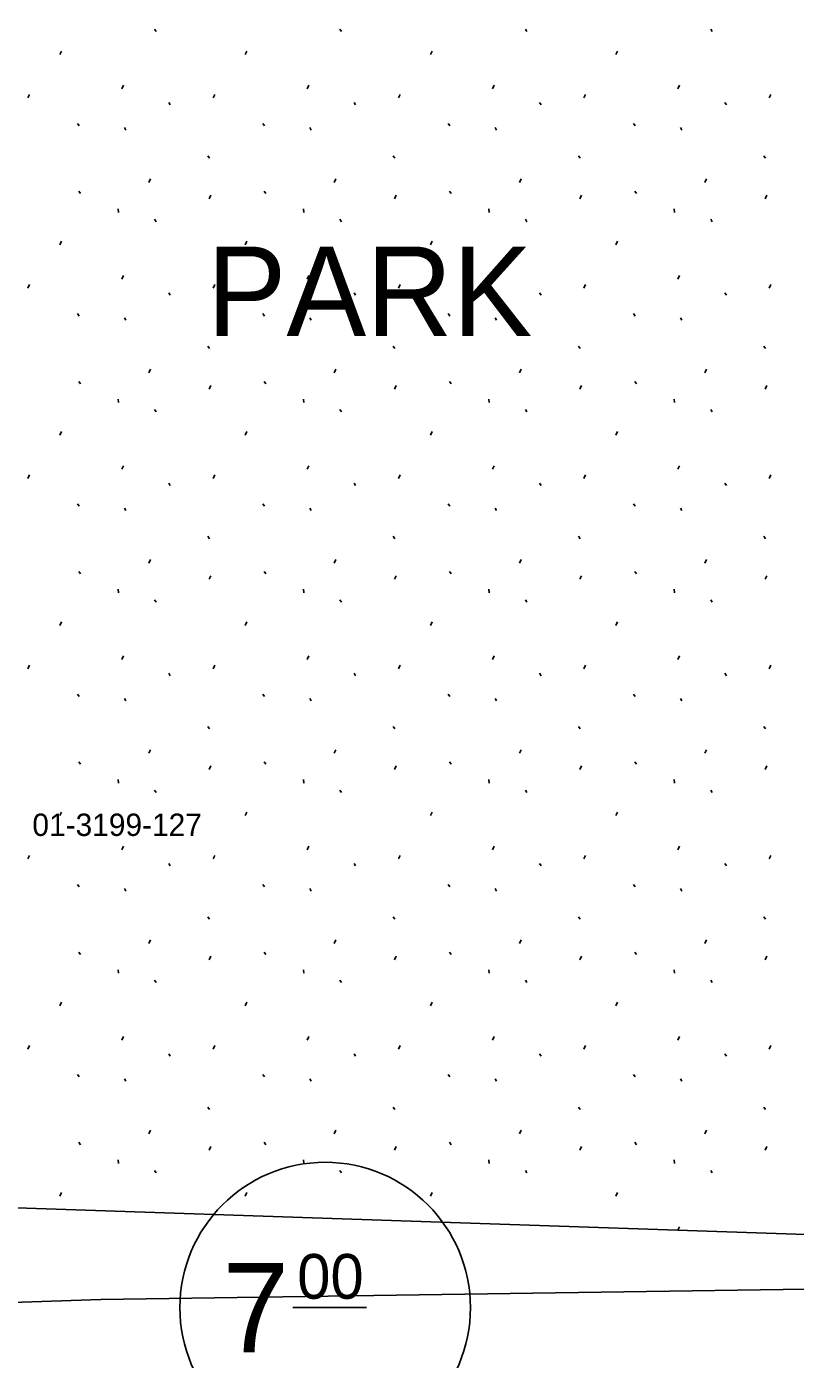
# Model space of a CAD drawing. Extents: x 419396 to 421519, y 4453567 to 4456767.
# Drawn here: x 421074.7 to 421109.1, y 4454902 to 4454961.6 of the extents above; entities that cross this region are included whole.
import ezdxf

# ---------------------------------------------------------------- set-up
doc = ezdxf.new("R2010")
doc.units = 0
for name, color, linetype in [('0_KADASTRO', 7, 'Continuous'), ('Level 28', 7, 'Continuous'), ('Level 41', 7, 'Continuous'), ('Level 58', 7, 'Continuous'), ('Level 61', 7, 'Continuous')]:
    doc.layers.add(name, color=color, linetype=linetype)

msp = doc.modelspace()

# ---------------------------------------------------------------- linework, layer by layer
at = {"layer": '0_KADASTRO'}
msp.add_lwpolyline([(421037.46, 4454903.29), (421040.2, 4454969.38), (421075.94, 4454970.4), (421108.85, 4454973.43), (421116.5, 4454972.91), (421125.86, 4454961.42), (421128.66, 4454942.34), (421125.36, 4454924.69), (421124.84, 4454912.07), (421127.9, 4454905.39), (421078.04, 4454904.65)], close=True, dxfattribs=at)
at = {"layer": 'Level 28'}
msp.add_line((421135.782, 4454906.666), (421051.306, 4454909.537), dxfattribs=at)
at = {"layer": 'Level 41'}
for p, q in [((421080.449, 4454961.486), (421080.519, 4454961.379)), ((421088.742, 4454961.486), (421088.812, 4454961.379)), ((421097.035, 4454961.486), (421097.105, 4454961.379)), ((421105.328, 4454961.486), (421105.398, 4454961.379)), ((421076.212, 4454960.342), (421076.284, 4454960.502)), ((421084.505, 4454960.342), (421084.577, 4454960.502)), ((421092.798, 4454960.342), (421092.87, 4454960.502)), ((421101.091, 4454960.342), (421101.163, 4454960.502)), ((421074.774, 4454958.404), (421074.845, 4454958.564)), ((421078.984, 4454958.812), (421079.054, 4454958.972)), ((421083.067, 4454958.404), (421083.138, 4454958.564)), ((421087.277, 4454958.812), (421087.347, 4454958.972)), ((421091.36, 4454958.404), (421091.431, 4454958.564)), ((421095.57, 4454958.812), (421095.64, 4454958.972)), ((421099.653, 4454958.404), (421099.724, 4454958.564)), ((421103.863, 4454958.812), (421103.933, 4454958.972)), ((421107.946, 4454958.404), (421108.017, 4454958.564)), ((421081.079, 4454958.196), (421081.15, 4454958.09)), ((421089.372, 4454958.196), (421089.443, 4454958.09)), ((421097.665, 4454958.196), (421097.736, 4454958.09)), ((421105.958, 4454958.196), (421106.029, 4454958.09)), ((421076.994, 4454957.267), (421077.065, 4454957.16)), ((421079.093, 4454957.075), (421079.164, 4454956.968)), ((421085.287, 4454957.267), (421085.358, 4454957.16)), ((421087.386, 4454957.075), (421087.457, 4454956.968)), ((421093.58, 4454957.267), (421093.651, 4454957.16)), ((421095.679, 4454957.075), (421095.75, 4454956.968)), ((421101.873, 4454957.267), (421101.944, 4454957.16)), ((421103.972, 4454957.075), (421104.043, 4454956.968)), ((421082.831, 4454955.814), (421082.902, 4454955.707)), ((421091.124, 4454955.814), (421091.195, 4454955.707)), ((421099.417, 4454955.814), (421099.488, 4454955.707)), ((421107.71, 4454955.814), (421107.781, 4454955.707)), ((421080.19, 4454954.621), (421080.261, 4454954.78)), ((421088.483, 4454954.621), (421088.554, 4454954.78)), ((421096.776, 4454954.621), (421096.847, 4454954.78)), ((421105.069, 4454954.621), (421105.14, 4454954.78)), ((421077.061, 4454954.237), (421077.132, 4454954.13)), ((421082.889, 4454953.892), (421082.961, 4454954.052)), ((421085.354, 4454954.237), (421085.425, 4454954.13)), ((421091.182, 4454953.892), (421091.254, 4454954.052)), ((421093.647, 4454954.237), (421093.718, 4454954.13)), ((421099.475, 4454953.892), (421099.547, 4454954.052)), ((421101.94, 4454954.237), (421102.011, 4454954.13)), ((421107.768, 4454953.892), (421107.84, 4454954.052)), ((421078.819, 4454953.446), (421078.837, 4454953.286)), ((421087.112, 4454953.446), (421087.13, 4454953.286)), ((421095.405, 4454953.446), (421095.423, 4454953.286)), ((421103.698, 4454953.446), (421103.716, 4454953.286)), ((421080.449, 4454952.976), (421080.519, 4454952.869)), ((421088.742, 4454952.976), (421088.812, 4454952.869)), ((421097.035, 4454952.976), (421097.105, 4454952.869)), ((421105.328, 4454952.976), (421105.398, 4454952.869)), ((421076.212, 4454951.832), (421076.284, 4454951.992)), ((421084.505, 4454951.832), (421084.577, 4454951.992)), ((421092.798, 4454951.832), (421092.87, 4454951.992)), ((421101.091, 4454951.832), (421101.163, 4454951.992)), ((421078.984, 4454950.302), (421079.054, 4454950.462)), ((421087.277, 4454950.302), (421087.347, 4454950.462)), ((421095.57, 4454950.302), (421095.64, 4454950.462)), ((421103.863, 4454950.302), (421103.933, 4454950.462)), ((421074.774, 4454949.894), (421074.845, 4454950.054)), ((421081.079, 4454949.686), (421081.15, 4454949.58)), ((421083.067, 4454949.894), (421083.138, 4454950.054)), ((421089.372, 4454949.686), (421089.443, 4454949.58)), ((421091.36, 4454949.894), (421091.431, 4454950.054)), ((421097.665, 4454949.686), (421097.736, 4454949.58)), ((421099.653, 4454949.894), (421099.724, 4454950.054)), ((421105.958, 4454949.686), (421106.029, 4454949.58)), ((421107.946, 4454949.894), (421108.017, 4454950.054)), ((421076.994, 4454948.757), (421077.065, 4454948.65)), ((421079.093, 4454948.565), (421079.164, 4454948.458)), ((421085.287, 4454948.757), (421085.358, 4454948.65)), ((421087.386, 4454948.565), (421087.457, 4454948.458)), ((421093.58, 4454948.757), (421093.651, 4454948.65)), ((421095.679, 4454948.565), (421095.75, 4454948.458)), ((421101.873, 4454948.757), (421101.944, 4454948.65)), ((421103.972, 4454948.565), (421104.043, 4454948.458)), ((421082.831, 4454947.304), (421082.902, 4454947.197)), ((421091.124, 4454947.304), (421091.195, 4454947.197)), ((421099.417, 4454947.304), (421099.488, 4454947.197)), ((421107.71, 4454947.304), (421107.781, 4454947.197)), ((421080.19, 4454946.111), (421080.261, 4454946.27)), ((421088.483, 4454946.111), (421088.554, 4454946.27)), ((421096.776, 4454946.111), (421096.847, 4454946.27)), ((421105.069, 4454946.111), (421105.14, 4454946.27)), ((421077.061, 4454945.727), (421077.132, 4454945.62)), ((421082.889, 4454945.382), (421082.961, 4454945.542)), ((421085.354, 4454945.727), (421085.425, 4454945.62)), ((421091.182, 4454945.382), (421091.254, 4454945.542)), ((421093.647, 4454945.727), (421093.718, 4454945.62)), ((421099.475, 4454945.382), (421099.547, 4454945.542)), ((421101.94, 4454945.727), (421102.011, 4454945.62)), ((421107.768, 4454945.382), (421107.84, 4454945.542)), ((421078.819, 4454944.936), (421078.837, 4454944.776)), ((421087.112, 4454944.936), (421087.13, 4454944.776)), ((421095.405, 4454944.936), (421095.423, 4454944.776)), ((421103.698, 4454944.936), (421103.716, 4454944.776)), ((421080.449, 4454944.466), (421080.519, 4454944.359)), ((421088.742, 4454944.466), (421088.812, 4454944.359)), ((421097.035, 4454944.466), (421097.105, 4454944.359)), ((421105.328, 4454944.466), (421105.398, 4454944.359)), ((421076.212, 4454943.322), (421076.284, 4454943.482)), ((421084.505, 4454943.322), (421084.577, 4454943.482)), ((421092.798, 4454943.322), (421092.87, 4454943.482)), ((421101.091, 4454943.322), (421101.163, 4454943.482)), ((421078.984, 4454941.792), (421079.054, 4454941.952)), ((421087.277, 4454941.792), (421087.347, 4454941.952)), ((421095.57, 4454941.792), (421095.64, 4454941.952)), ((421103.863, 4454941.792), (421103.933, 4454941.952)), ((421074.774, 4454941.384), (421074.845, 4454941.544)), ((421083.067, 4454941.384), (421083.138, 4454941.544)), ((421091.36, 4454941.384), (421091.431, 4454941.544)), ((421099.653, 4454941.384), (421099.724, 4454941.544)), ((421107.946, 4454941.384), (421108.017, 4454941.544)), ((421081.079, 4454941.176), (421081.15, 4454941.07)), ((421089.372, 4454941.176), (421089.443, 4454941.07)), ((421097.665, 4454941.176), (421097.736, 4454941.07)), ((421105.958, 4454941.176), (421106.029, 4454941.07)), ((421076.994, 4454940.247), (421077.065, 4454940.14)), ((421085.287, 4454940.247), (421085.358, 4454940.14)), ((421093.58, 4454940.247), (421093.651, 4454940.14)), ((421101.873, 4454940.247), (421101.944, 4454940.14)), ((421079.093, 4454940.055), (421079.164, 4454939.948)), ((421087.386, 4454940.055), (421087.457, 4454939.948)), ((421095.679, 4454940.055), (421095.75, 4454939.948)), ((421103.972, 4454940.055), (421104.043, 4454939.948)), ((421082.831, 4454938.794), (421082.902, 4454938.687)), ((421091.124, 4454938.794), (421091.195, 4454938.687)), ((421099.417, 4454938.794), (421099.488, 4454938.687)), ((421107.71, 4454938.794), (421107.781, 4454938.687)), ((421080.19, 4454937.601), (421080.261, 4454937.76)), ((421088.483, 4454937.601), (421088.554, 4454937.76)), ((421096.776, 4454937.601), (421096.847, 4454937.76)), ((421105.069, 4454937.601), (421105.14, 4454937.76)), ((421077.061, 4454937.217), (421077.132, 4454937.11)), ((421085.354, 4454937.217), (421085.425, 4454937.11)), ((421093.647, 4454937.217), (421093.718, 4454937.11)), ((421101.94, 4454937.217), (421102.011, 4454937.11)), ((421082.889, 4454936.872), (421082.961, 4454937.032)), ((421091.182, 4454936.872), (421091.254, 4454937.032)), ((421099.475, 4454936.872), (421099.547, 4454937.032)), ((421107.768, 4454936.872), (421107.84, 4454937.032)), ((421078.819, 4454936.426), (421078.837, 4454936.266)), ((421080.449, 4454935.956), (421080.519, 4454935.849)), ((421087.112, 4454936.426), (421087.13, 4454936.266)), ((421088.742, 4454935.956), (421088.812, 4454935.849)), ((421095.405, 4454936.426), (421095.423, 4454936.266)), ((421097.035, 4454935.956), (421097.105, 4454935.849)), ((421103.698, 4454936.426), (421103.716, 4454936.266)), ((421105.328, 4454935.956), (421105.398, 4454935.849)), ((421076.212, 4454934.812), (421076.284, 4454934.972)), ((421084.505, 4454934.812), (421084.577, 4454934.972)), ((421092.798, 4454934.812), (421092.87, 4454934.972)), ((421101.091, 4454934.812), (421101.163, 4454934.972)), ((421074.774, 4454932.874), (421074.845, 4454933.034)), ((421078.984, 4454933.282), (421079.054, 4454933.442)), ((421083.067, 4454932.874), (421083.138, 4454933.034)), ((421087.277, 4454933.282), (421087.347, 4454933.442)), ((421091.36, 4454932.874), (421091.431, 4454933.034)), ((421095.57, 4454933.282), (421095.64, 4454933.442)), ((421099.653, 4454932.874), (421099.724, 4454933.034)), ((421103.863, 4454933.282), (421103.933, 4454933.442)), ((421107.946, 4454932.874), (421108.017, 4454933.034)), ((421081.079, 4454932.666), (421081.15, 4454932.56)), ((421089.372, 4454932.666), (421089.443, 4454932.56)), ((421097.665, 4454932.666), (421097.736, 4454932.56)), ((421105.958, 4454932.666), (421106.029, 4454932.56)), ((421076.994, 4454931.737), (421077.065, 4454931.63)), ((421085.287, 4454931.737), (421085.358, 4454931.63)), ((421093.58, 4454931.737), (421093.651, 4454931.63)), ((421101.873, 4454931.737), (421101.944, 4454931.63)), ((421079.093, 4454931.545), (421079.164, 4454931.438)), ((421087.386, 4454931.545), (421087.457, 4454931.438)), ((421095.679, 4454931.545), (421095.75, 4454931.438)), ((421103.972, 4454931.545), (421104.043, 4454931.438)), ((421082.831, 4454930.284), (421082.902, 4454930.177)), ((421091.124, 4454930.284), (421091.195, 4454930.177)), ((421099.417, 4454930.284), (421099.488, 4454930.177)), ((421107.71, 4454930.284), (421107.781, 4454930.177)), ((421080.19, 4454929.091), (421080.261, 4454929.25)), ((421088.483, 4454929.091), (421088.554, 4454929.25)), ((421096.776, 4454929.091), (421096.847, 4454929.25)), ((421105.069, 4454929.091), (421105.14, 4454929.25)), ((421077.061, 4454928.707), (421077.132, 4454928.6)), ((421082.889, 4454928.362), (421082.961, 4454928.522)), ((421085.354, 4454928.707), (421085.425, 4454928.6)), ((421091.182, 4454928.362), (421091.254, 4454928.522)), ((421093.647, 4454928.707), (421093.718, 4454928.6)), ((421099.475, 4454928.362), (421099.547, 4454928.522)), ((421101.94, 4454928.707), (421102.011, 4454928.6)), ((421107.768, 4454928.362), (421107.84, 4454928.522)), ((421078.819, 4454927.916), (421078.837, 4454927.756)), ((421087.112, 4454927.916), (421087.13, 4454927.756)), ((421095.405, 4454927.916), (421095.423, 4454927.756)), ((421103.698, 4454927.916), (421103.716, 4454927.756)), ((421080.449, 4454927.446), (421080.519, 4454927.339)), ((421088.742, 4454927.446), (421088.812, 4454927.339)), ((421097.035, 4454927.446), (421097.105, 4454927.339)), ((421105.328, 4454927.446), (421105.398, 4454927.339)), ((421076.212, 4454926.302), (421076.284, 4454926.462)), ((421084.505, 4454926.302), (421084.577, 4454926.462)), ((421092.798, 4454926.302), (421092.87, 4454926.462)), ((421101.091, 4454926.302), (421101.163, 4454926.462)), ((421078.984, 4454924.772), (421079.054, 4454924.932)), ((421087.277, 4454924.772), (421087.347, 4454924.932)), ((421095.57, 4454924.772), (421095.64, 4454924.932)), ((421103.863, 4454924.772), (421103.933, 4454924.932)), ((421074.774, 4454924.364), (421074.845, 4454924.524)), ((421081.079, 4454924.156), (421081.15, 4454924.05)), ((421083.067, 4454924.364), (421083.138, 4454924.524)), ((421089.372, 4454924.156), (421089.443, 4454924.05)), ((421091.36, 4454924.364), (421091.431, 4454924.524)), ((421097.665, 4454924.156), (421097.736, 4454924.05)), ((421099.653, 4454924.364), (421099.724, 4454924.524)), ((421105.958, 4454924.156), (421106.029, 4454924.05)), ((421107.946, 4454924.364), (421108.017, 4454924.524)), ((421076.994, 4454923.227), (421077.065, 4454923.12)), ((421079.093, 4454923.035), (421079.164, 4454922.928)), ((421085.287, 4454923.227), (421085.358, 4454923.12)), ((421087.386, 4454923.035), (421087.457, 4454922.928)), ((421093.58, 4454923.227), (421093.651, 4454923.12)), ((421095.679, 4454923.035), (421095.75, 4454922.928)), ((421101.873, 4454923.227), (421101.944, 4454923.12)), ((421103.972, 4454923.035), (421104.043, 4454922.928)), ((421082.831, 4454921.774), (421082.902, 4454921.667)), ((421091.124, 4454921.774), (421091.195, 4454921.667)), ((421099.417, 4454921.774), (421099.488, 4454921.667)), ((421107.71, 4454921.774), (421107.781, 4454921.667)), ((421080.19, 4454920.581), (421080.261, 4454920.74)), ((421088.483, 4454920.581), (421088.554, 4454920.74)), ((421096.776, 4454920.581), (421096.847, 4454920.74)), ((421105.069, 4454920.581), (421105.14, 4454920.74)), ((421077.061, 4454920.197), (421077.132, 4454920.09)), ((421082.889, 4454919.852), (421082.961, 4454920.012)), ((421085.354, 4454920.197), (421085.425, 4454920.09)), ((421091.182, 4454919.852), (421091.254, 4454920.012)), ((421093.647, 4454920.197), (421093.718, 4454920.09)), ((421099.475, 4454919.852), (421099.547, 4454920.012)), ((421101.94, 4454920.197), (421102.011, 4454920.09)), ((421107.768, 4454919.852), (421107.84, 4454920.012)), ((421078.819, 4454919.406), (421078.837, 4454919.246)), ((421087.112, 4454919.406), (421087.13, 4454919.246)), ((421095.405, 4454919.406), (421095.423, 4454919.246)), ((421103.698, 4454919.406), (421103.716, 4454919.246)), ((421080.449, 4454918.936), (421080.519, 4454918.829)), ((421088.742, 4454918.936), (421088.812, 4454918.829)), ((421097.035, 4454918.936), (421097.105, 4454918.829)), ((421105.328, 4454918.936), (421105.398, 4454918.829)), ((421076.212, 4454917.792), (421076.284, 4454917.952)), ((421084.505, 4454917.792), (421084.577, 4454917.952)), ((421092.798, 4454917.792), (421092.87, 4454917.952)), ((421101.091, 4454917.792), (421101.163, 4454917.952)), ((421078.984, 4454916.262), (421079.054, 4454916.422)), ((421087.277, 4454916.262), (421087.347, 4454916.422)), ((421095.57, 4454916.262), (421095.64, 4454916.422)), ((421103.863, 4454916.262), (421103.933, 4454916.422)), ((421074.774, 4454915.854), (421074.845, 4454916.014)), ((421081.079, 4454915.646), (421081.15, 4454915.54)), ((421083.067, 4454915.854), (421083.138, 4454916.014)), ((421089.372, 4454915.646), (421089.443, 4454915.54)), ((421091.36, 4454915.854), (421091.431, 4454916.014)), ((421097.665, 4454915.646), (421097.736, 4454915.54)), ((421099.653, 4454915.854), (421099.724, 4454916.014)), ((421105.958, 4454915.646), (421106.029, 4454915.54)), ((421107.946, 4454915.854), (421108.017, 4454916.014)), ((421076.994, 4454914.717), (421077.065, 4454914.61)), ((421079.093, 4454914.525), (421079.164, 4454914.418)), ((421085.287, 4454914.717), (421085.358, 4454914.61)), ((421087.386, 4454914.525), (421087.457, 4454914.418)), ((421093.58, 4454914.717), (421093.651, 4454914.61)), ((421095.679, 4454914.525), (421095.75, 4454914.418)), ((421101.873, 4454914.717), (421101.944, 4454914.61)), ((421103.972, 4454914.525), (421104.043, 4454914.418)), ((421082.831, 4454913.264), (421082.902, 4454913.157)), ((421091.124, 4454913.264), (421091.195, 4454913.157)), ((421099.417, 4454913.264), (421099.488, 4454913.157)), ((421107.71, 4454913.264), (421107.781, 4454913.157)), ((421080.19, 4454912.071), (421080.261, 4454912.23)), ((421088.483, 4454912.071), (421088.554, 4454912.23)), ((421096.776, 4454912.071), (421096.847, 4454912.23)), ((421105.069, 4454912.071), (421105.14, 4454912.23)), ((421077.061, 4454911.687), (421077.132, 4454911.58)), ((421082.889, 4454911.342), (421082.961, 4454911.502)), ((421085.354, 4454911.687), (421085.425, 4454911.58)), ((421091.182, 4454911.342), (421091.254, 4454911.502)), ((421093.647, 4454911.687), (421093.718, 4454911.58)), ((421099.475, 4454911.342), (421099.547, 4454911.502)), ((421101.94, 4454911.687), (421102.011, 4454911.58)), ((421107.768, 4454911.342), (421107.84, 4454911.502)), ((421078.819, 4454910.896), (421078.837, 4454910.736)), ((421087.112, 4454910.896), (421087.13, 4454910.736)), ((421095.405, 4454910.896), (421095.423, 4454910.736)), ((421103.698, 4454910.896), (421103.716, 4454910.736)), ((421080.449, 4454910.426), (421080.519, 4454910.319)), ((421088.742, 4454910.426), (421088.812, 4454910.319)), ((421097.035, 4454910.426), (421097.105, 4454910.319)), ((421105.328, 4454910.426), (421105.398, 4454910.319)), ((421076.212, 4454909.282), (421076.284, 4454909.442)), ((421084.505, 4454909.282), (421084.577, 4454909.442)), ((421092.798, 4454909.282), (421092.87, 4454909.442)), ((421101.091, 4454909.282), (421101.163, 4454909.442)), ((421103.863, 4454907.752), (421103.933, 4454907.912))]:
    msp.add_line(p, q, dxfattribs=at)
at = {"layer": 'Level 58'}
msp.add_line((421086.629, 4454904.292), (421089.926, 4454904.292), dxfattribs=at)
msp.add_circle((421088.078, 4454904.292), 6.5, dxfattribs=at)

# ---------------------------------------------------------------- texts
at = {"layer": '0_KADASTRO'}
msp.add_text('01-3199-127', height=1, dxfattribs=at).set_placement((421074.978, 4454925.391))
at = {"layer": 'Level 58'}
for s, height, p in [('00', 1.9983, (421086.829, 4454904.691)), ('7', 3.997, (421083.482, 4454902.293))]:
    msp.add_text(s, height=height, dxfattribs=at).set_placement(p)
at = {"layer": 'Level 61'}
msp.add_text('PARK', height=4, dxfattribs=at).set_placement((421082.778, 4454947.758))

doc.saveas('drawing.dxf')
